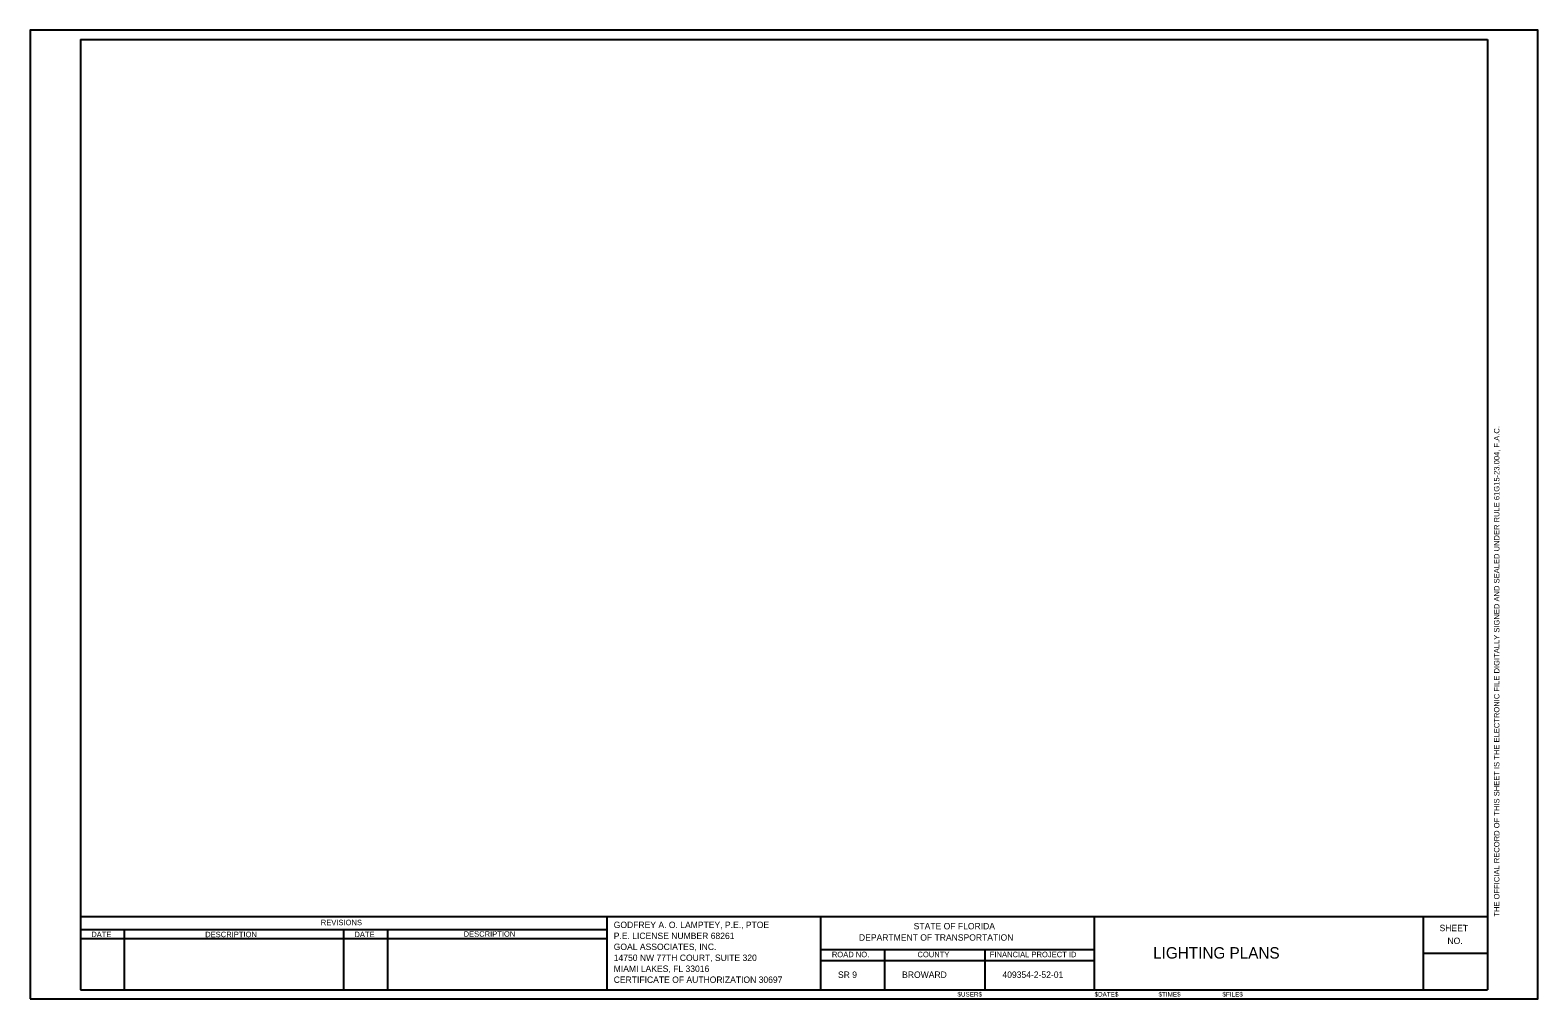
# Model space of a CAD drawing. Extents: x -816.7 to -800.2, y -2197.9 to -2187.3.
import ezdxf

# ---------------------------------------------------------------- set-up
doc = ezdxf.new("R2010")
doc.units = 0
for name, color, linetype in [('AdhocPoint_dp', 7, 'Continuous'), ('PlotBorder_dp', 7, 'Continuous'), ('SheetBorder_dp', 7, 'Continuous'), ('SheetLines_dp', 7, 'Continuous'), ('TextLabel', 7, 'Continuous'), ('TextMinor', 7, 'Continuous'), ('TextMisc', 7, 'Continuous'), ('TextTitle', 7, 'Continuous')]:
    doc.layers.add(name, color=color, linetype=linetype)

msp = doc.modelspace()

# ---------------------------------------------------------------- linework, layer by layer
at = {"layer": 'AdhocPoint_dp'}
msp.add_line((-816.669, -2197.899), (-816.669, -2197.899), dxfattribs=at)
msp.add_line((-816.669, -2197.899), (-816.669, -2197.899), dxfattribs=at)
at = {"layer": 'PlotBorder_dp'}
msp.add_lwpolyline([(-816.669, -2197.899), (-800.169, -2197.899), (-800.169, -2187.299), (-816.669, -2187.299)], close=True, dxfattribs=at)
at = {"layer": 'SheetBorder_dp'}
for p, q in [((-816.119, -2187.399), (-816.119, -2197.799)), ((-816.119, -2187.399), (-800.719, -2187.399)), ((-800.719, -2187.399), (-800.719, -2197.799)), ((-816.119, -2196.999), (-800.719, -2196.999)), ((-816.119, -2197.799), (-800.719, -2197.799))]:
    msp.add_line(p, q, dxfattribs=at)
at = {"layer": 'SheetLines_dp'}
for p, q in [((-816.119, -2197.139), (-810.359, -2197.139)), ((-815.639, -2197.139), (-815.639, -2197.799)), ((-813.239, -2197.139), (-813.239, -2197.799)), ((-812.759, -2197.139), (-812.759, -2197.799)), ((-810.359, -2196.999), (-810.359, -2197.799)), ((-808.019, -2196.999), (-808.019, -2197.799)), ((-805.019, -2197.799), (-805.019, -2196.999)), ((-801.419, -2197.799), (-801.419, -2196.999)), ((-816.119, -2197.239), (-810.359, -2197.239)), ((-808.019, -2197.359), (-805.019, -2197.359)), ((-807.319, -2197.359), (-807.319, -2197.799)), ((-806.219, -2197.359), (-806.219, -2197.799)), ((-801.419, -2197.399), (-800.719, -2197.399)), ((-808.019, -2197.479), (-805.019, -2197.479))]:
    msp.add_line(p, q, dxfattribs=at)

# ---------------------------------------------------------------- texts
at = {"layer": 'TextLabel'}
msp.add_text('        LIGHTING PLANS         ', height=0.125, dxfattribs=at).set_placement((-804.75, -2197.458))
at = {"layer": 'TextMinor'}
for s, height, rotation, p in [('THE OFFICIAL RECORD OF THIS SHEET IS THE ELECTRONIC FILE DIGITALLY SIGNED AND SEALED UNDER RULE 61G15-23.004, F.A.C.', 0.06, 90, (-800.589, -2196.999)), ('$DATE$', 0.05, 360, (-805.02, -2197.874)), ('$TIME$', 0.05, 360, (-804.32, -2197.874)), ('$FILE$', 0.05, 360, (-803.62, -2197.874))]:
    msp.add_text(s, height=height, rotation=rotation, dxfattribs=at).set_placement(p)
msp.add_text('$USER$', height=0.05, dxfattribs=at).set_placement((-806.52, -2197.874))
at = {"layer": 'TextMisc'}
for s, height, p in [('REVISIONS', 0.06, (-813.488, -2197.093)), ('STATE OF FLORIDA', 0.07, (-806.999, -2197.138)), ('DEPARTMENT OF TRANSPORTATION', 0.07, (-807.598, -2197.262)), ('ROAD NO.', 0.06, (-807.895, -2197.443)), ('COUNTY', 0.06, (-806.958, -2197.443)), ('FINANCIAL PROJECT ID', 0.06, (-806.166, -2197.443)), (' SR 9  ', 0.07, (-807.854, -2197.669)), ('  BROWARD   ', 0.07, (-807.178, -2197.669)), ('409354-2-52-01', 0.07, (-806.028, -2197.669))]:
    msp.add_text(s, height=height, dxfattribs=at).set_placement(p)
for s, height, rotation, p in [('SHEET', 0.07, 359.8607, (-801.244, -2197.158)), ('DATE', 0.06, 359.8693, (-816, -2197.223)), ('DESCRIPTION', 0.06, 0.0498, (-814.753, -2197.224)), ('DATE', 0.06, 359.8693, (-813.12, -2197.223)), ('DESCRIPTION', 0.06, 0.0498, (-811.925, -2197.219)), ('NO.', 0.07, 359.8607, (-801.158, -2197.298))]:
    msp.add_text(s, height=height, rotation=rotation, dxfattribs=at).set_placement(p)
at = {"layer": 'TextTitle'}
for s, p in [('GODFREY A. O. LAMPTEY, P.E., PTOE', (-810.282, -2197.124)), ('GOAL ASSOCIATES, INC.', (-810.282, -2197.364)), ('P.E. LICENSE NUMBER 68261', (-810.282, -2197.244)), ('14750 NW 77TH COURT, SUITE 320', (-810.282, -2197.484)), ('MIAMI LAKES, FL 33016', (-810.282, -2197.604)), ('CERTIFICATE OF AUTHORIZATION 30697', (-810.282, -2197.724))]:
    msp.add_text(s, height=0.07, dxfattribs=at).set_placement(p)

doc.saveas('drawing.dxf')
